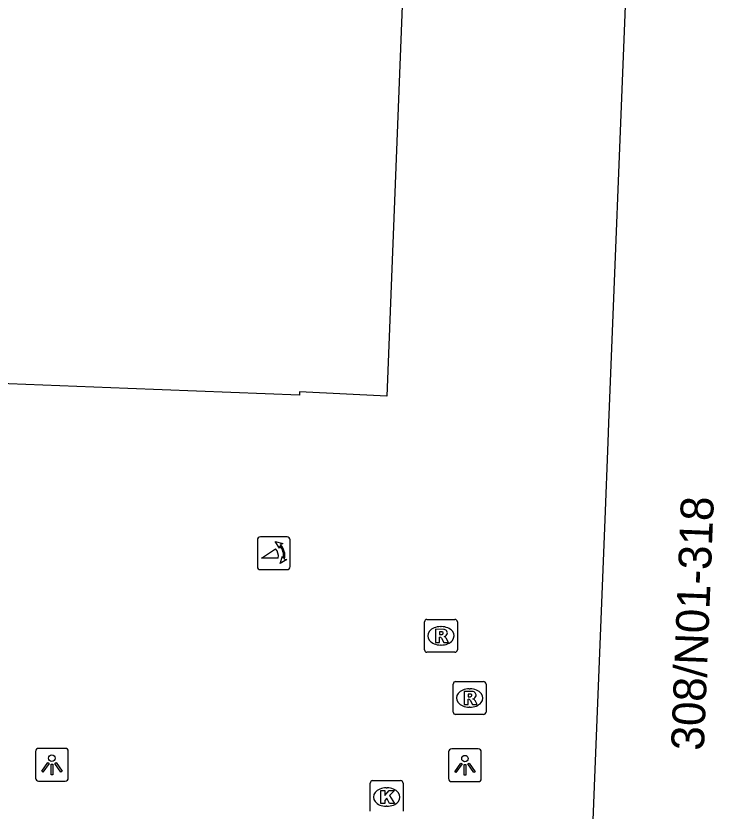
# Model space of a CAD drawing. Extents: x 160891 to 161384, y 386490 to 386907.
# Drawn here: x 161269.97 to 161291.22, y 386804.6 to 386828.79 of the extents above; entities that cross this region are included whole.
import ezdxf

# ---------------------------------------------------------------- set-up
doc = ezdxf.new("R2010")
doc.units = 0
for name, color, linetype in [('IMGEO_Kolk', 7, 'Continuous'), ('IMGEO_Lichtpunt', 7, 'Continuous'), ('IMGEO_Pand', 7, 'Continuous'), ('IMGEO_Pand_nummerreeks', 7, 'Continuous'), ('IMGEO_Poller', 7, 'Continuous'), ('IMGEO_Rioolput', 7, 'Continuous')]:
    doc.layers.add(name, color=color, linetype=linetype)

msp = doc.modelspace()

# ---------------------------------------------------------------- linework, layer by layer
at = {"layer": 'IMGEO_Kolk'}
for p, q in [((161280.752, 386804.599), (161280.752, 386805.451)), ((161280.827, 386805.525), (161281.679, 386805.525)), ((161281.24, 386805.305), (161281.265, 386805.305)), ((161281.753, 386805.451), (161281.753, 386804.599)), ((161281.263, 386804.745), (161281.238, 386804.745))]:
    msp.add_line(p, q, dxfattribs=at)
for points in [[(161280.752, 386804.599), (161280.752, 386805.451)], [(161280.827, 386805.525), (161281.679, 386805.525)], [(161281.753, 386805.451), (161281.753, 386804.599)], [(161281.073, 386805.225), (161281.196, 386805.225), (161281.196, 386805.074), (161281.326, 386805.225), (161281.49, 386805.225), (161281.344, 386805.074), (161281.497, 386804.825), (161281.345, 386804.825), (161281.26, 386804.989), (161281.196, 386804.922), (161281.196, 386804.825), (161281.073, 386804.825), (161281.073, 386805.225)]]:
    msp.add_lwpolyline(points, dxfattribs=at)
for centre, start, end in [((161280.829, 386805.449), 91.552, 178.448), ((161280.829, 386805.449), 91.552, 178.448), ((161281.677, 386805.449), 1.552, 88.448), ((161281.677, 386805.449), 1.552, 88.448)]:
    msp.add_arc(centre, 0.0765, start, end, dxfattribs=at)
for centre, major_axis, ratio, start_param, end_param in [((161281.239, 386805.025), (-0.387, 0.002), 0.722429, 4.712389, 7.853982), ((161281.264, 386805.025), (-0.39, 0.002), 0.717154, 1.570796, 4.712389)]:
    msp.add_ellipse(centre, major_axis=major_axis, ratio=ratio, start_param=start_param, end_param=end_param, dxfattribs=at)
at = {"layer": 'IMGEO_Lichtpunt'}
for p, q in [((161271.47, 386806.507), (161270.662, 386806.507)), ((161271.47, 386806.507), (161270.662, 386806.507)), ((161270.568, 386806.412), (161270.568, 386805.605)), ((161270.568, 386806.412), (161270.568, 386805.605)), ((161271.564, 386805.605), (161271.564, 386806.412)), ((161271.564, 386805.605), (161271.564, 386806.412)), ((161283.138, 386806.397), (161283.138, 386805.59)), ((161283.138, 386806.397), (161283.138, 386805.59)), ((161284.04, 386806.492), (161283.232, 386806.492)), ((161284.04, 386806.492), (161283.232, 386806.492)), ((161284.134, 386805.59), (161284.134, 386806.397)), ((161284.134, 386805.59), (161284.134, 386806.397)), ((161270.662, 386805.511), (161271.47, 386805.511)), ((161270.662, 386805.511), (161271.47, 386805.511)), ((161283.232, 386805.496), (161284.04, 386805.496)), ((161283.232, 386805.496), (161284.04, 386805.496))]:
    msp.add_line(p, q, dxfattribs=at)
for points in [[(161270.942, 386806.076), (161270.981, 386806.048), (161270.793, 386805.786), (161270.755, 386805.813), (161270.942, 386806.076)], [(161271.044, 386806.028), (161271.091, 386806.028), (161271.091, 386805.706), (161271.044, 386805.706), (161271.044, 386806.028)], [(161271.154, 386806.048), (161271.192, 386806.075), (161271.379, 386805.813), (161271.34, 386805.785), (161271.154, 386806.048)], [(161283.512, 386806.061), (161283.551, 386806.033), (161283.363, 386805.771), (161283.325, 386805.798), (161283.512, 386806.061)], [(161283.724, 386806.033), (161283.762, 386806.06), (161283.949, 386805.798), (161283.91, 386805.77), (161283.724, 386806.033)], [(161283.614, 386806.013), (161283.661, 386806.013), (161283.661, 386805.691), (161283.614, 386805.691), (161283.614, 386806.013)]]:
    msp.add_lwpolyline(points, dxfattribs=at)
for centre in [(161271.067, 386806.21), (161283.637, 386806.195)]:
    msp.add_circle(centre, 0.0994, dxfattribs=at)
for centre, start, end in [((161270.662, 386806.412), 90, 180), ((161270.662, 386806.412), 90, 180), ((161271.47, 386806.412), 0, 90), ((161271.47, 386806.412), 0, 90), ((161283.232, 386806.397), 90, 180), ((161283.232, 386806.397), 90, 180), ((161284.04, 386806.397), 0, 90), ((161284.04, 386806.397), 0, 90), ((161270.662, 386805.605), 180, 270), ((161270.662, 386805.605), 180, 270), ((161271.47, 386805.605), 270, 0), ((161271.47, 386805.605), 270, 360), ((161283.232, 386805.59), 180, 270), ((161283.232, 386805.59), 180, 270), ((161284.04, 386805.59), 270, 0), ((161284.04, 386805.59), 270, 360)]:
    msp.add_arc(centre, 0.0946, start, end, dxfattribs=at)
at = {"layer": 'IMGEO_Pand'}
for points in [[(161286.841, 386786.774), (161286.896, 386788.152), (161287.138, 386794.242), (161287.589, 386805.614), (161287.9, 386813.473), (161287.994, 386815.819), (161288.017, 386816.411), (161288.037, 386816.903), (161288.513, 386828.834), (161288.608, 386831.222), (161288.895, 386838.421)], [(161281.723, 386829.096), (161281.256, 386817.22), (161278.605, 386817.352), (161278.601, 386817.252), (161273.381, 386817.451), (161268.706, 386817.64), (161259.254, 386818.021), (161251.986, 386818.314), (161237.554, 386818.897), (161223.022, 386819.483), (161215.857, 386819.772), (161201.32, 386820.359)]]:
    msp.add_lwpolyline(points, dxfattribs=at)
at = {"layer": 'IMGEO_Poller'}
for p, q in [((161277.321, 386812.847), (161277.321, 386812.04)), ((161277.321, 386812.847), (161277.321, 386812.04)), ((161278.223, 386812.942), (161277.415, 386812.942)), ((161278.223, 386812.942), (161277.415, 386812.942)), ((161278.317, 386812.04), (161278.317, 386812.847)), ((161278.317, 386812.04), (161278.317, 386812.847)), ((161277.415, 386811.945), (161278.223, 386811.945)), ((161277.415, 386811.945), (161278.223, 386811.945))]:
    msp.add_line(p, q, dxfattribs=at)
for points in [[(161278, 386812.671), (161277.988, 386812.598), (161277.863, 386812.803)], [(161277.863, 386812.803), (161278.094, 386812.737), (161278.023, 386812.705)], [(161277.956, 386812.298), (161277.443, 386812.298), (161277.873, 386812.573)], [(161278.016, 386812.126), (161278.082, 386812.357), (161278.112, 386812.289)], [(161278.148, 386812.262), (161278.22, 386812.251), (161278.016, 386812.126)]]:
    msp.add_lwpolyline(points, dxfattribs=at)
for centre, radius, start, end in [((161277.415, 386812.847), 0.0946, 90, 180), ((161277.415, 386812.847), 0.0946, 90, 180), ((161278.223, 386812.847), 0.0946, 0, 90), ((161278.223, 386812.847), 0.0946, 0, 90), ((161277.628, 386812.348), 0.332, 351.3247, 42.4854), ((161277.642, 386812.358), 0.476, 351.7527, 41.1691), ((161277.642, 386812.358), 0.516, 349.3569, 42.2912), ((161277.415, 386812.04), 0.0946, 180, 270), ((161277.415, 386812.04), 0.0946, 180, 270), ((161278.223, 386812.04), 0.0946, 270, 0), ((161278.223, 386812.04), 0.0946, 270, 0)]:
    msp.add_arc(centre, radius, start, end, dxfattribs=at)
at = {"layer": 'IMGEO_Rioolput'}
for p, q in [((161282.479, 386810.43), (161283.331, 386810.43)), ((161282.404, 386809.504), (161282.404, 386810.356)), ((161282.892, 386810.21), (161282.917, 386810.21)), ((161283.405, 386810.356), (161283.405, 386809.504)), ((161282.915, 386809.65), (161282.89, 386809.65)), ((161283.331, 386809.43), (161282.479, 386809.43)), ((161283.277, 386807.613), (161283.277, 386808.465)), ((161283.352, 386808.539), (161284.204, 386808.539)), ((161284.278, 386808.465), (161284.278, 386807.613)), ((161283.765, 386808.319), (161283.79, 386808.319)), ((161283.788, 386807.759), (161283.763, 386807.759)), ((161284.204, 386807.539), (161283.352, 386807.539))]:
    msp.add_line(p, q, dxfattribs=at)
for points in [[(161282.479, 386810.43), (161283.331, 386810.43)], [(161282.404, 386809.504), (161282.404, 386810.356)], [(161283.405, 386810.356), (161283.405, 386809.504)], [(161282.993, 386810.128), (161282.741, 386810.13), (161282.741, 386809.73)], [(161282.741, 386809.73), (161282.865, 386809.73), (161282.865, 386809.892), (161282.876, 386809.892)], [(161282.919, 386810.049), (161282.865, 386810.049), (161282.865, 386809.968)], [(161282.865, 386809.968), (161282.917, 386809.968)], [(161282.923, 386809.863), (161282.994, 386809.73), (161283.134, 386809.73), (161283.069, 386809.856)], [(161283.331, 386809.43), (161282.479, 386809.43)], [(161283.277, 386807.613), (161283.277, 386808.465)], [(161283.352, 386808.539), (161284.204, 386808.539)], [(161284.278, 386808.465), (161284.278, 386807.613)], [(161283.866, 386808.237), (161283.614, 386808.239), (161283.614, 386807.839)], [(161283.614, 386807.839), (161283.738, 386807.839), (161283.738, 386808.001), (161283.749, 386808.001)], [(161283.792, 386808.158), (161283.738, 386808.158), (161283.738, 386808.077)], [(161283.738, 386808.077), (161283.79, 386808.077)], [(161283.796, 386807.972), (161283.867, 386807.839), (161284.007, 386807.839), (161283.942, 386807.965)], [(161284.204, 386807.539), (161283.352, 386807.539)]]:
    msp.add_lwpolyline(points, dxfattribs=at)
for centre, radius, start, end in [((161282.481, 386810.354), 0.0765, 91.552, 178.448), ((161282.481, 386810.354), 0.0765, 91.552, 178.448), ((161283.329, 386810.354), 0.0765, 1.552, 88.448), ((161283.329, 386810.354), 0.0765, 1.552, 88.448), ((161282.875, 386809.839), 0.0533, 26.0293, 88.6989), ((161282.901, 386810.157), 0.19, 274.7715, 282.9687), ((161282.925, 386809.953), 0.0964, 77.0061, 93.1865), ((161282.939, 386810.01), 0.0378, 276.6634, 79.6772), ((161282.992, 386810.018), 0.109, 350.3612, 89.416), ((161282.99, 386810.018), 0.112, 277.5842, 350.9817), ((161282.974, 386809.803), 0.108, 29.5134, 73.7905), ((161282.481, 386809.506), 0.0765, 181.552, 268.448), ((161282.481, 386809.506), 0.0765, 181.552, 268.448), ((161283.329, 386809.506), 0.0765, 271.552, 358.448), ((161283.329, 386809.506), 0.0765, 271.552, 358.448), ((161283.354, 386808.463), 0.0765, 91.552, 178.448), ((161283.354, 386808.463), 0.0765, 91.552, 178.448), ((161284.202, 386808.463), 0.0765, 1.552, 88.448), ((161284.202, 386808.463), 0.0765, 1.552, 88.448), ((161283.865, 386808.127), 0.109, 350.3612, 89.416), ((161283.748, 386807.948), 0.0533, 26.0293, 88.6989), ((161283.774, 386808.266), 0.19, 274.7715, 282.9687), ((161283.798, 386808.062), 0.0964, 77.0061, 93.1865), ((161283.812, 386808.119), 0.0378, 276.6634, 79.6772), ((161283.863, 386808.127), 0.112, 277.5842, 350.9817), ((161283.847, 386807.912), 0.108, 29.5134, 73.7905), ((161283.354, 386807.615), 0.0765, 181.552, 268.448), ((161283.354, 386807.615), 0.0765, 181.552, 268.448), ((161284.202, 386807.615), 0.0765, 271.552, 358.448), ((161284.202, 386807.615), 0.0765, 271.552, 358.448)]:
    msp.add_arc(centre, radius, start, end, dxfattribs=at)
for centre, major_axis, ratio, start_param, end_param in [((161282.891, 386809.93), (-0.387, 0.002), 0.722429, 4.712389, 7.853982), ((161282.916, 386809.93), (-0.39, 0.002), 0.717154, 1.570796, 4.712389), ((161283.764, 386808.039), (-0.387, 0.002), 0.722429, 4.712389, 7.853982), ((161283.789, 386808.039), (-0.39, 0.002), 0.717154, 1.570796, 4.712389)]:
    msp.add_ellipse(centre, major_axis=major_axis, ratio=ratio, start_param=start_param, end_param=end_param, dxfattribs=at)

# ---------------------------------------------------------------- texts
at = {"layer": 'IMGEO_Pand_nummerreeks'}
msp.add_text('308/N01-318', height=1, rotation=87.7256, dxfattribs=at).set_placement((161290.906, 386806.426))

doc.saveas('drawing.dxf')
